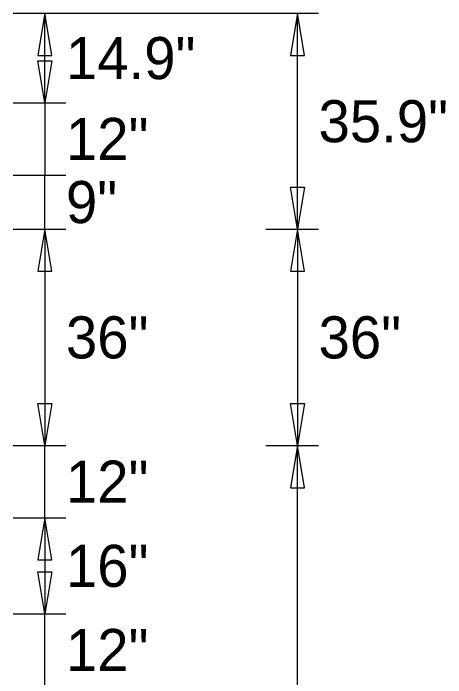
# Model space of a CAD drawing. Extents: x 2149961 to 2150220, y 145114 to 145240.
# Drawn here: x 2150213.7 to 2150219.69, y 145137.61 to 145146.82 of the extents above; entities that cross this region are included whole.
import ezdxf

# ---------------------------------------------------------------- set-up
doc = ezdxf.new("R2010")
doc.units = 0
doc.layers.add('GSDIMS', color=7, linetype='Continuous')

msp = doc.modelspace()

# ---------------------------------------------------------------- linework, layer by layer
at = {"layer": 'GSDIMS'}
for p, q in [((2150213.7019, 145146.8167), (2150214.4311, 145146.8167)), ((2150213.7019, 145146.8167), (2150217.2019, 145146.8167)), ((2150214.1394, 145145.5749), (2150214.1394, 145146.8167)), ((2150217.2019, 145146.8167), (2150217.9311, 145146.8167)), ((2150217.6394, 145143.825), (2150217.6394, 145146.8167)), ((2150213.7019, 145145.5749), (2150214.4311, 145145.5749)), ((2150213.7019, 145145.5749), (2150214.4311, 145145.5749)), ((2150214.1394, 145145.5749), (2150214.1394, 145144.5749)), ((2150213.7019, 145144.5749), (2150214.4311, 145144.5749)), ((2150213.7019, 145144.5749), (2150214.4311, 145144.5749)), ((2150214.1394, 145143.825), (2150214.1394, 145144.5749)), ((2150213.7019, 145143.825), (2150214.4311, 145143.825)), ((2150213.7019, 145143.825), (2150214.4311, 145143.825)), ((2150214.1394, 145143.825), (2150214.1394, 145140.8249)), ((2150217.2019, 145143.825), (2150217.9311, 145143.825)), ((2150217.2019, 145143.825), (2150217.9311, 145143.825)), ((2150217.6394, 145143.825), (2150217.6394, 145140.8249)), ((2150213.7019, 145140.8249), (2150214.4311, 145140.8249)), ((2150213.7019, 145140.8249), (2150214.4311, 145140.8249)), ((2150214.1394, 145139.8249), (2150214.1394, 145140.8249)), ((2150217.2019, 145140.8249), (2150217.9311, 145140.8249)), ((2150217.2019, 145140.8249), (2150217.9311, 145140.8249)), ((2150217.6394, 145130.3166), (2150217.6394, 145140.8249)), ((2150213.7019, 145139.8249), (2150214.4311, 145139.8249)), ((2150213.7019, 145139.8249), (2150214.4311, 145139.8249)), ((2150214.1394, 145139.8249), (2150214.1394, 145138.4916)), ((2150213.7019, 145138.4916), (2150214.4311, 145138.4916)), ((2150213.7019, 145138.4916), (2150214.4311, 145138.4916)), ((2150214.1394, 145137.4916), (2150214.1394, 145138.4916))]:
    msp.add_line(p, q, dxfattribs=at)
for points in [[(2150214.1394, 145146.8167), (2150214.0422, 145146.2333), (2150214.2366, 145146.2333)], [(2150217.6394, 145146.8167), (2150217.5422, 145146.2333), (2150217.7366, 145146.2333)], [(2150214.1394, 145145.5749), (2150214.0422, 145146.1583), (2150214.2366, 145146.1583)], [(2150217.6394, 145143.825), (2150217.5422, 145144.4083), (2150217.7366, 145144.4083)], [(2150214.1394, 145143.825), (2150214.0422, 145143.2416), (2150214.2366, 145143.2416)], [(2150217.6394, 145143.825), (2150217.5422, 145143.2416), (2150217.7366, 145143.2416)], [(2150214.1394, 145140.8249), (2150214.0422, 145141.4082), (2150214.2366, 145141.4082)], [(2150217.6394, 145140.8249), (2150217.5422, 145141.4082), (2150217.7366, 145141.4082)], [(2150217.6394, 145140.8249), (2150217.5422, 145140.2415), (2150217.7366, 145140.2415)], [(2150214.1394, 145139.8249), (2150214.0422, 145139.2416), (2150214.2366, 145139.2416)], [(2150214.1394, 145138.4916), (2150214.0422, 145139.0749), (2150214.2366, 145139.0749)]]:
    msp.add_lwpolyline(points, close=True, dxfattribs=at)

# ---------------------------------------------------------------- texts
for s, p in [('14.9"', (2150214.4311, 145145.9041)), ('35.9"', (2150217.9311, 145145.0291)), ('12"', (2150214.4311, 145144.7833)), ('9"', (2150214.4311, 145143.9083)), ('36"', (2150214.4311, 145142.0332)), ('36"', (2150217.9311, 145142.0332)), ('12"', (2150214.4311, 145140.0332)), ('16"', (2150214.4311, 145138.8666)), ('12"', (2150214.4311, 145137.6999))]:
    msp.add_text(s, height=0.58333, dxfattribs=at).set_placement(p)

doc.saveas('drawing.dxf')
